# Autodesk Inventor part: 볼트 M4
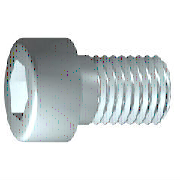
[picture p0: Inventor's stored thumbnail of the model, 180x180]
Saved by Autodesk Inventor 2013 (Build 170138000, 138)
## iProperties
IsCustomPart: 1
Created: 2012-02
Part Number: 볼트 M4
Material: 스테인리스강
Description: 6각 소켓 머리 캡 나사
Document SubType Name: Modeling
Standard: ISO 4762
Designer: mduedu
Standard Revision: Fourth edition 2004-03-01
Standards Organization: ISO
Language: ko-KR
Size Designation: M4 x 10
Categories: <MemberInstance><Categories><Category DisplayName="조임쇠" InternalName="e4da775c-781d-43d5-af7c-5136215cf5a6" Mnemonic="FSTN"><Category DisplayName="볼트" InternalN
Density: 8.08 g/cm^3
Mass: 2.0939 g
Surface Area: 3.06255 cm^2
Volume: 0.259146 cm^3
Author: mduedu
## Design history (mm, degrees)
sketch "스케치1"
  geometry: L1 (-1, 0)-(10, 0); L2 (10, 0)-(10, 2); L3 (10, 2)-(1.75, 2); L4 (1.75, 2)-(1.32, 2); L5 (1.32, 2)-(0, 2); L6 (0, 2)-(0, 3.5); L7 (0, 3.5)-(-4, 3.5); L8 (-4, 3.5)-(-4, 1.732); L9 (-4, 1.732)-(-2, 1.732); L10 (-2, 1.732)-(-1, 0); L11 (-6.8, 0)-(12.8, 0) reference; L12 (0, -0.7)-(0, 4.2) reference; L13 (1.75, 2)-(0, 2)
  constraints: 22 end point, 6 parallel, 2 collinear, 2 perpendicular, 1 horizontal, 1 point on line
  dimensions: "d1" = 8.25 distance from line of L3.end L2 (= GEL); "d2" = 0.42952 distance of L4.end L3.end (computed from GAL); "d3" = 4 distance between parallel lines of L8 L6 (= KOH); "d4" = 2 distance of L8.end L9.end (= INTI); "d5" = 60 deg angle of L10 L1; "d6" = 4 diameter of L3 L1 (= GD); "d7" = 4 diameter of L5 L1 (= BDM); "d8" = 3.4641 diameter of L9 L1 (= 1.1547 x SW); "d9" = 7 diameter of L7 L1 (= KOD); "d26" = 10 distance between parallel lines of L12 L2 (= NLG)
revolve "본체" sketch "스케치1" stored, may be unused: angle "d10" = 90 deg
sketch "스케치2"
  geometry: L1 (0, -4.9)-(0, 4.9) reference; L2 (-4.9, 0)-(4.9, 0) reference; L3 (1.732, 0)-(0.866, -1.5); L4 (0.866, -1.5)-(-0.866, -1.5); L5 (-0.866, -1.5)-(-1.732, 0); L6 (-1.732, 0)-(-0.866, 1.5); L7 (-0.866, 1.5)-(0.866, 1.5); L8 (0.866, 1.5)-(1.732, 0); 2 further points
  constraints: 12 end point, 1 coincident, 1 horizontal alignment, 1 point on line, 12 other
extrude "슬롯" join sketch "스케치2" stored distance "d11" = 10; taper "d12" = 0 deg
workplane "Work Plane1"
body "Solid1"
fillet "모깎기1" dims "d17" = 0.4 (= RR)
feature "스레드" dims "d13" = 8.25 (= GEL), "d14" = 0
chamfer "모따기1" distance "d15" = 0.42941 (= -0.5 x SPD + 0.5 x GD); stored, may be unused: second distance "d16" = 0.42941 (= GUL), angle "d27" = 45 deg
other parameters: "GD" = 4 [user parameter; used in 2 equation terms], "NLG" = 10 [user parameter; used in 1 equation term], "GEL" = 8.25 [user parameter; used in 2 equation terms], "KOD" = 7 [user parameter; used in 1 equation term], "KOH" = 4 [user parameter; used in 1 equation term], "INTI" = 2 [user parameter; used in 1 equation term], "GAL" = 0.42941 (= 0.61345 x PTC) [user parameter; used in 1 equation term], "GUL" = 0.42941 (= 0.61345 x PTC) [user parameter; used in 1 equation term], "BDM" = 4 (= NND) [user parameter; used in 1 equation term], "SW" = 3 [user parameter; used in 2 equation terms], "RR" = 0.4 [user parameter; used in 1 equation term], "SPD" = 3.14117 (= NND - 1.2269 x PTC) [user parameter; used in 1 equation term], "d19" = 0, "d28" = 0, "d29" = 0, "R" = 0.1 [user parameter], "TOA" = 30 deg [user parameter], "GD1" = 3.14117 (= THREADDIA - 1.2269 x PTC) [user parameter], "THREADDIA" = 4 [user parameter; used in 1 equation term], "FAWI" = 45 deg [user parameter], "TPU" = 14.28571 (computed from PTC) [user parameter], "PTC" = 0.7 [user parameter; used in 5 equation terms], "NND" = 4 [user parameter; used in 2 equation terms], "E0" = 3.465 (= 1.155 x SW) [user parameter]
